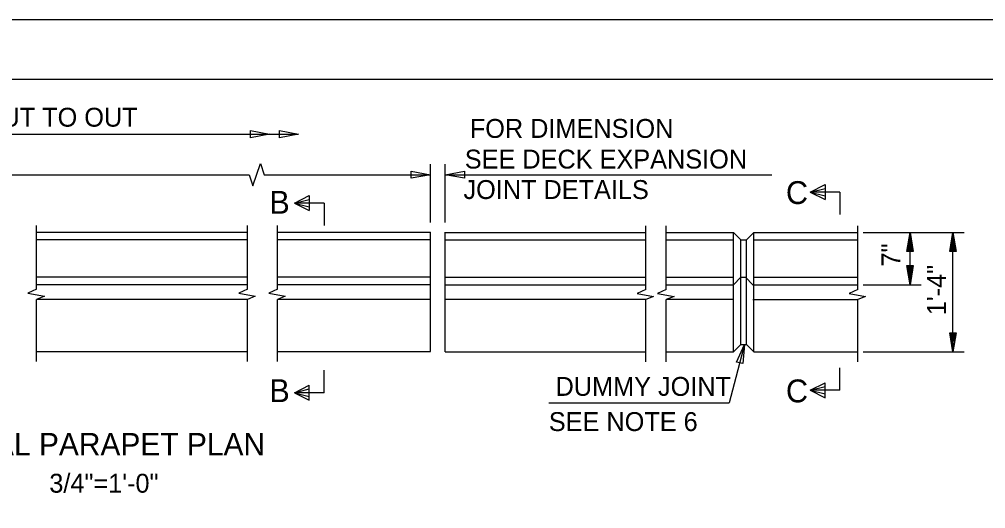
# Model space of a CAD drawing. Extents: x 0 to 34, y 0 to 23.5.
# Drawn here: x 7.85 to 15.94, y 17.9 to 22 of the extents above; entities that cross this region are included whole.
import ezdxf

# ---------------------------------------------------------------- set-up
doc = ezdxf.new("R2010")
doc.units = 0
for name, color, linetype in [('BORDER_ANNO_Cutsheet', 7, 'Continuous'), ('BRDG_ANNO_Anno-Sheet', 7, 'Continuous'), ('BRDG_ANNO_General-Notes', 7, 'Continuous'), ('BRDG_BASE_Obj-Line', 7, 'Continuous')]:
    doc.layers.add(name, color=color, linetype=linetype)

msp = doc.modelspace()

# ---------------------------------------------------------------- linework, layer by layer
at = {"layer": 'BORDER_ANNO_Cutsheet'}
msp.add_lwpolyline([(0, 22), (34, 22), (34, 0), (0, 0)], close=True, dxfattribs=at)
at = {"layer": 'BRDG_ANNO_Anno-Sheet'}
msp.add_lwpolyline([(1.5, 21.5), (33.5, 21.5), (33.5, 0.5), (1.5, 0.5)], close=True, dxfattribs=at)
at = {"layer": 'BRDG_ANNO_General-Notes'}
for p, q in [((9.7839, 21.0087), (9.7839, 21.0687)), ((9.7839, 21.0687), (9.9439, 21.0388)), ((10.0269, 21.0087), (10.0269, 21.0687)), ((10.0269, 21.0687), (10.1869, 21.0388)), ((2.9781, 21.0388), (10.1869, 21.0388)), ((9.9439, 21.0388), (9.7839, 21.0087)), ((10.1869, 21.0388), (10.0269, 21.0087)), ((11.1306, 20.6683), (11.1306, 20.7283)), ((11.1306, 20.7283), (11.2906, 20.6983)), ((11.2906, 20.2985), (11.2906, 20.7858)), ((11.4156, 20.2985), (11.4156, 20.7858)), ((11.4156, 20.6983), (11.5756, 20.7283)), ((11.5756, 20.7283), (11.5756, 20.6683)), ((5.9781, 20.6983), (9.7726, 20.6983)), ((9.8976, 20.6983), (11.2906, 20.6983)), ((11.2906, 20.6983), (11.1306, 20.6683)), ((11.4156, 20.6983), (14.1521, 20.6983)), ((11.5756, 20.6683), (11.4156, 20.6983)), ((14.4728, 20.5532), (14.5978, 20.6157)), ((14.4728, 20.5532), (14.5978, 20.5844)), ((14.5978, 20.6157), (14.5978, 20.5532)), ((10.1511, 20.4609), (10.2761, 20.5234)), ((10.1511, 20.4609), (10.2761, 20.4921)), ((10.2761, 20.5234), (10.2761, 20.4609)), ((14.7228, 20.5532), (14.4728, 20.5532)), ((14.4728, 20.5532), (14.5978, 20.4907)), ((14.4728, 20.5532), (14.5978, 20.5219)), ((14.5978, 20.5532), (14.5978, 20.4907)), ((14.7228, 20.5532), (14.7228, 20.3657)), ((10.4011, 20.4609), (10.1511, 20.4609)), ((10.1511, 20.4609), (10.2761, 20.3984)), ((10.1511, 20.4609), (10.2761, 20.4296)), ((10.2761, 20.4609), (10.2761, 20.3984)), ((10.4011, 20.4609), (10.4011, 20.2734)), ((14.9156, 20.2151), (15.7633, 20.2151)), ((15.2889, 20.0595), (15.3065, 20.1665)), ((15.3098, 19.7776), (15.3098, 20.2151)), ((15.3307, 20.0595), (15.3131, 20.1665)), ((15.6486, 20.0595), (15.6662, 20.1665)), ((15.6696, 19.2151), (15.6696, 20.2151)), ((15.6905, 20.0595), (15.6729, 20.1665)), ((15.2948, 20.0595), (15.306, 20.1271)), ((15.3021, 20.0599), (15.3059, 20.0993)), ((15.3247, 20.0595), (15.3136, 20.1271)), ((15.3174, 20.0599), (15.3136, 20.0993)), ((15.6546, 20.0595), (15.6658, 20.1271)), ((15.6619, 20.0599), (15.6657, 20.0993)), ((15.6845, 20.0595), (15.6734, 20.1271)), ((15.6772, 20.0599), (15.6734, 20.0993)), ((15.2889, 19.9332), (15.3065, 19.8262)), ((15.2948, 19.9332), (15.306, 19.8656)), ((15.3021, 19.9328), (15.3059, 19.8934)), ((15.3307, 19.9332), (15.3131, 19.8262)), ((15.3247, 19.9332), (15.3136, 19.8656)), ((15.3174, 19.9328), (15.3136, 19.8934)), ((14.9156, 19.7776), (15.4035, 19.7776)), ((15.6486, 19.3707), (15.6662, 19.2637)), ((15.6546, 19.3707), (15.6658, 19.3031)), ((15.6619, 19.3703), (15.6657, 19.3309)), ((15.6905, 19.3707), (15.6729, 19.2637)), ((15.6845, 19.3707), (15.6734, 19.3031)), ((15.6772, 19.3703), (15.6734, 19.3309)), ((13.9222, 19.2776), (13.7952, 18.7874)), ((13.8563, 19.1294), (13.9222, 19.2776)), ((13.9222, 19.2776), (13.9079, 19.116)), ((14.9156, 19.2151), (15.7633, 19.2151)), ((13.9079, 19.116), (13.8563, 19.1294)), ((10.4011, 18.8728), (10.4011, 19.0603)), ((14.7228, 18.8935), (14.7228, 19.081)), ((14.4728, 18.8935), (14.5978, 18.956)), ((14.5978, 18.8935), (14.5978, 18.956)), ((10.1511, 18.8728), (10.2761, 18.9353)), ((10.1511, 18.8728), (10.2761, 18.9041)), ((10.4011, 18.8728), (10.1511, 18.8728)), ((10.1511, 18.8728), (10.2761, 18.8103)), ((10.1511, 18.8728), (10.2761, 18.8416)), ((10.2761, 18.8728), (10.2761, 18.9353)), ((10.2761, 18.8103), (10.2761, 18.8728)), ((14.4728, 18.8935), (14.5978, 18.9247)), ((14.7228, 18.8935), (14.4728, 18.8935)), ((14.4728, 18.8935), (14.5978, 18.831)), ((14.4728, 18.8935), (14.5978, 18.8622)), ((14.5978, 18.831), (14.5978, 18.8935)), ((12.2829, 18.7874), (13.7952, 18.7874))]:
    msp.add_line(p, q, dxfattribs=at)
msp.add_lwpolyline([(9.7726, 20.6983), (9.8039, 20.6046), (9.8664, 20.7921), (9.8976, 20.6983)], dxfattribs=at)
for points in [[(15.2834, 20.0551), (15.3098, 20.2151), (15.3362, 20.0551)], [(15.6432, 20.0551), (15.6696, 20.2151), (15.696, 20.0551)], [(15.3362, 19.9376), (15.3098, 19.7776), (15.2834, 19.9376)], [(15.696, 19.3751), (15.6696, 19.2151), (15.6432, 19.3751)]]:
    msp.add_lwpolyline(points, close=True, dxfattribs=at)
at = {"layer": 'BRDG_BASE_Obj-Line'}
for p, q in [((7.9915, 19.74), (7.9915, 20.2737)), ((9.7574, 19.74), (9.7574, 20.2737)), ((10.0093, 19.74), (10.0093, 20.2737)), ((13.0953, 19.738), (13.0953, 20.2718)), ((13.2671, 19.738), (13.2671, 20.2718)), ((14.8723, 19.738), (14.8723, 20.2718)), ((7.9915, 20.2171), (9.7574, 20.2171)), ((10.0093, 20.2171), (11.2906, 20.2171)), ((11.2906, 19.2171), (11.2906, 20.2171)), ((11.4156, 19.2151), (11.4156, 20.2171)), ((11.4156, 20.2151), (13.0953, 20.2151)), ((13.2671, 20.2151), (13.8296, 20.2151)), ((13.8296, 19.2151), (13.8296, 20.2151)), ((13.8921, 20.1526), (13.8296, 20.2151)), ((13.939, 20.1526), (14.0015, 20.2151)), ((14.0015, 20.2151), (14.8723, 20.2151)), ((14.0015, 19.2151), (14.0015, 20.2151)), ((7.9915, 20.1546), (9.7574, 20.1546)), ((10.0093, 20.1546), (11.2906, 20.1546)), ((11.4156, 20.1526), (13.0953, 20.1526)), ((13.2671, 20.1526), (13.8296, 20.1526)), ((13.8921, 19.2776), (13.8921, 20.1526)), ((13.8921, 20.1526), (13.939, 20.1526)), ((13.939, 19.2776), (13.939, 20.1526)), ((14.0015, 20.1526), (14.8723, 20.1526)), ((7.9915, 19.8421), (9.7574, 19.8421)), ((10.0093, 19.8421), (11.2906, 19.8421)), ((11.4156, 19.8401), (13.0953, 19.8401)), ((13.2671, 19.8401), (13.8296, 19.8401)), ((13.8296, 19.7776), (13.8921, 19.8401)), ((13.8921, 19.8401), (13.9312, 19.8401)), ((13.9937, 19.7776), (13.9312, 19.8401)), ((14.0015, 19.8401), (14.8723, 19.8401)), ((7.9915, 19.7796), (9.7574, 19.7796)), ((10.0093, 19.7796), (11.2906, 19.7796)), ((11.4156, 19.7776), (13.0953, 19.7776)), ((13.2671, 19.7776), (13.8296, 19.7776)), ((13.9937, 19.7776), (14.8723, 19.7776)), ((7.9915, 19.74), (7.9186, 19.7067)), ((7.9186, 19.7067), (8.0567, 19.6808)), ((8.0567, 19.6808), (7.9915, 19.6546)), ((9.7574, 19.74), (9.6846, 19.7067)), ((9.6846, 19.7067), (9.8226, 19.6808)), ((9.8226, 19.6808), (9.7574, 19.6546)), ((10.0093, 19.74), (9.9365, 19.7067)), ((9.9365, 19.7067), (10.0745, 19.6808)), ((10.0745, 19.6808), (10.0093, 19.6546)), ((13.0953, 19.738), (13.0224, 19.7047)), ((13.0224, 19.7047), (13.1605, 19.6789)), ((13.1605, 19.6789), (13.0953, 19.6526)), ((13.2671, 19.738), (13.1943, 19.7047)), ((13.1943, 19.7047), (13.3323, 19.6789)), ((13.3323, 19.6789), (13.2671, 19.6526)), ((14.8723, 19.738), (14.7995, 19.7047)), ((14.7995, 19.7047), (14.9375, 19.6789)), ((14.9375, 19.6789), (14.8723, 19.6526)), ((7.9915, 19.1342), (7.9915, 19.6546)), ((9.7574, 19.6546), (7.9915, 19.6546)), ((9.7574, 19.1342), (9.7574, 19.6546)), ((10.0093, 19.1342), (10.0093, 19.6546)), ((11.2906, 19.6546), (10.0093, 19.6546)), ((13.0953, 19.6526), (11.4156, 19.6526)), ((13.0953, 19.1322), (13.0953, 19.6526)), ((13.2671, 19.1322), (13.2671, 19.6526)), ((13.8296, 19.6526), (13.2671, 19.6526)), ((13.9937, 19.6526), (14.8723, 19.6526)), ((14.8723, 19.1322), (14.8723, 19.6526)), ((13.8296, 19.2151), (13.8921, 19.2776)), ((13.8921, 19.2776), (13.939, 19.2776)), ((14.0015, 19.2151), (13.939, 19.2776)), ((7.9915, 19.2171), (9.7574, 19.2171)), ((10.0093, 19.2171), (11.2906, 19.2171)), ((11.4156, 19.2151), (13.0953, 19.2151)), ((13.2671, 19.2151), (13.8296, 19.2151)), ((14.0015, 19.2151), (14.8723, 19.2151))]:
    msp.add_line(p, q, dxfattribs=at)

# ---------------------------------------------------------------- texts
at = {"layer": 'BRDG_ANNO_General-Notes'}
for s, height, p in [('PARAPET PAY LENGTH _______ OUT TO OUT', 0.158333, (4.2018, 21.101)), ('FOR DIMENSION', 0.158333, (11.6209, 21.0071)), ('SEE DECK EXPANSION', 0.158333, (11.5791, 20.7503)), ('JOINT DETAILS', 0.158333, (11.568, 20.4952)), ('C', 0.1917, (14.2697, 20.4529)), ('B', 0.1917, (9.9412, 20.3717)), ('B', 0.1917, (9.9412, 18.7941)), ('DUMMY JOINT', 0.158333, (12.3395, 18.8465)), ('C', 0.1917, (14.2697, 18.7919)), ('SEE NOTE 6', 0.15833, (12.2831, 18.5517)), ('PARTIAL PARAPET PLAN', 0.1875, (6.8959, 18.3479)), ('3/4"=1\'-0"', 0.15833, (8.0978, 18.0354))]:
    msp.add_text(s, height=height, dxfattribs=at).set_placement(p)
for s, p in [('7"', (15.2286, 19.9298)), ('1\'-4"', (15.6107, 19.5218))]:
    msp.add_text(s, height=0.15833, rotation=90, dxfattribs=at).set_placement(p)

doc.saveas('drawing.dxf')
